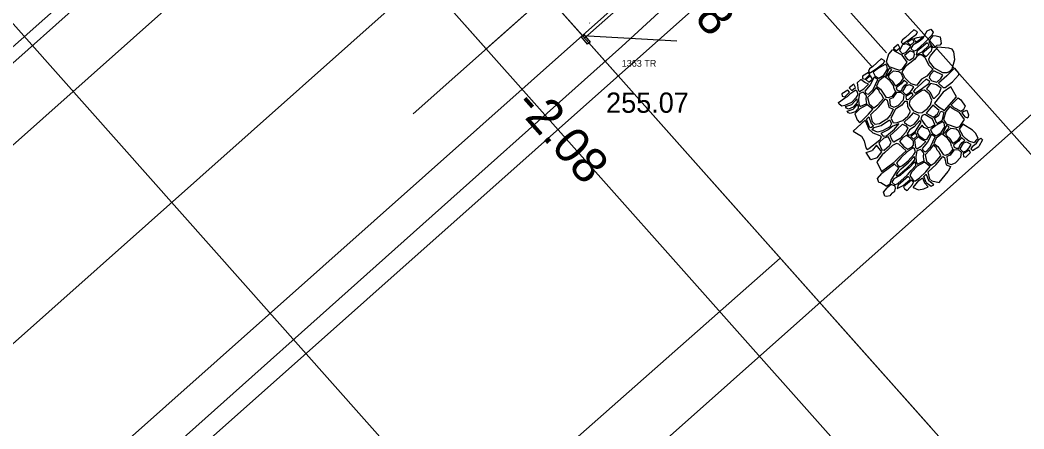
# Model space of a CAD drawing. Extents: x 49683 to 58852, y 49525 to 54803.
# Drawn here: x 53855 to 54003.9, y 51774.1 to 51834.7 of the extents above; entities that cross this region are included whole.
import ezdxf

# ---------------------------------------------------------------- set-up
doc = ezdxf.new("R2010")
doc.units = 0
for name, color, linetype in [('Level 11', 7, 'Continuous'), ('Level 13', 7, 'Continuous'), ('Level 15', 7, 'Continuous'), ('Level 16', 7, 'Continuous'), ('Level 19', 7, 'Continuous'), ('Level 20', 7, 'Continuous'), ('Level 27', 7, 'Continuous'), ('Level 29', 7, 'Continuous'), ('Level 3', 7, 'Continuous'), ('Level 32', 7, 'Continuous'), ('Level 33', 7, 'Continuous'), ('Level 5', 7, 'Continuous'), ('Level 50', 7, 'Continuous'), ('Level 53', 7, 'Continuous'), ('Level 61', 7, 'Continuous'), ('Level 63', 7, 'Continuous'), ('Level 8', 7, 'Continuous')]:
    doc.layers.add(name, color=color, linetype=linetype)

msp = doc.modelspace()

# ---------------------------------------------------------------- linework, layer by layer
at = {"layer": 'Level 11'}
for p, q in [((53944.24, 51830.77), (54450.3, 52297.6)), ((53245.86, 51207.55), (53944.24, 51830.77))]:
    msp.add_line(p, q, dxfattribs=at)
at = {"layer": 'Level 13'}
msp.add_line((53681.55, 51593.39), (53996.93, 51873.72), dxfattribs=at)
at = {"layer": 'Level 15'}
for p, q in [((53460.73, 51466.68), (53909.18, 51865.3)), ((53938.41, 51832.41), (53909.18, 51865.3)), ((53953.36, 51845.7), (53938.41, 51832.41)), ((53939.46, 51834.29), (53939.52, 51834.21)), ((53938.41, 51832.41), (53489.97, 51433.79)), ((53938.41, 51832.41), (53952.39, 51831.59))]:
    msp.add_line(p, q, dxfattribs=at)
at = {"layer": 'Level 16'}
for points in [[(53988.15, 51832.94), (53987.57, 51833.26), (53986.35, 51832.1), (53985.88, 51831.74), (53985.69, 51831.42), (53985.94, 51831.17), (53987.03, 51831.91), (53987.96, 51832.6)], [(53987.36, 51831.91), (53986.66, 51831.37), (53987.08, 51830.98), (53987.62, 51831.44)], [(53985.24, 51831.05), (53984.55, 51830.52), (53984.96, 51830.12), (53985.51, 51830.58)], [(53987.12, 51830.84), (53986.46, 51831.16), (53985.92, 51831.03), (53985.44, 51830.19), (53985.92, 51829.68), (53986.46, 51829.95), (53986.81, 51830.34)], [(53986.19, 51829.44), (53986.63, 51828.83), (53986.95, 51828.73), (53987.56, 51829.15), (53987.69, 51829.59), (53987.63, 51829.9), (53987.04, 51830.14)], [(53989.58, 51831.31), (53988.08, 51830.06), (53987.95, 51829.55), (53988.82, 51829.98), (53989.83, 51830.9), (53989.82, 51831.06)], [(53990.08, 51830.81), (53988.88, 51829.78), (53989, 51829.51), (53989.43, 51829.27), (53990.21, 51830.13), (53990.32, 51830.51)], [(53983.28, 51828.64), (53982.71, 51828.96), (53981.49, 51827.81), (53981.02, 51827.44), (53980.83, 51827.12), (53981.08, 51826.87), (53982.17, 51827.61), (53983.09, 51828.3)], [(53983.32, 51828.09), (53982.36, 51827.56), (53981.53, 51826.94), (53981.84, 51826.39), (53982.37, 51826.06), (53983.15, 51826.52), (53983.65, 51827.39), (53983.58, 51827.93)], [(53983.9, 51827.54), (53983.36, 51826.44), (53983.54, 51826.38), (53984.14, 51827.08), (53984.32, 51827.37)], [(53986.01, 51826.05), (53985.51, 51825.31), (53984.91, 51824.88), (53984.47, 51825.59), (53983.9, 51826.07), (53983.84, 51826.35), (53984.02, 51826.66), (53984.55, 51827.16), (53985.37, 51827.05), (53985.63, 51826.84)], [(53991.9, 51826.5), (53990.56, 51827.17), (53989.99, 51826.58), (53989.86, 51826.12), (53990.23, 51825.67), (53990.97, 51825.5), (53991.57, 51826.02)], [(53979.72, 51825.87), (53979.17, 51825.39), (53979.3, 51824.3), (53979.54, 51824.09), (53980.18, 51824.48), (53980.85, 51825.19), (53980.3, 51825.43)], [(53980.84, 51826.92), (53979.95, 51826.38), (53979.98, 51826.02), (53980.36, 51825.93), (53981.06, 51826.62)], [(53981.71, 51826.23), (53981.08, 51825.07), (53980.29, 51824.17), (53980.48, 51823.8), (53980.83, 51823.69), (53981.53, 51824.38), (53982.22, 51825.9)], [(53981.17, 51826.41), (53980.47, 51825.87), (53980.89, 51825.48), (53981.43, 51825.94)], [(53986.15, 51825.8), (53985.72, 51825.24), (53984.94, 51824.65), (53985.05, 51824.33), (53985.37, 51824.18), (53985.76, 51824.19), (53985.89, 51824.58), (53986.23, 51825.06), (53986.65, 51825.34)], [(53989.98, 51825.6), (53989.4, 51825.93), (53988.18, 51824.77), (53987.71, 51824.4), (53987.52, 51824.09), (53987.77, 51823.84), (53988.86, 51824.57), (53989.79, 51825.27)], [(53977.81, 51824.3), (53976.92, 51823.75), (53976.94, 51823.4), (53977.33, 51823.3), (53978.03, 51824)], [(53978.67, 51825.17), (53977.98, 51824.64), (53978.39, 51824.25), (53978.94, 51824.7)], [(53980.05, 51824.02), (53979.54, 51823.8), (53979.36, 51822.97), (53979.44, 51822.2), (53979.63, 51821.85), (53980.6, 51822.33), (53980.53, 51822.92), (53980.55, 51823.45)], [(53981.92, 51824.66), (53981.4, 51823.92), (53980.73, 51823.21), (53980.94, 51822.28), (53981.65, 51821.67), (53982.26, 51822.1), (53983.06, 51823.07), (53982.82, 51823.62), (53982.53, 51823.91), (53982.39, 51824.3)], [(53987.59, 51824.77), (53986.93, 51825.1), (53986.4, 51824.96), (53985.91, 51824.12), (53986.4, 51823.61), (53986.93, 51823.88), (53987.28, 51824.27)], [(53989.18, 51824.3), (53988.83, 51824.23), (53987.76, 51823.53), (53986.98, 51822.75), (53986.89, 51822.3), (53987.01, 51821.99), (53987.5, 51821.3), (53988.26, 51820.91), (53988.83, 51820.97), (53989.59, 51821.56), (53990.04, 51822.14), (53990.24, 51822.8), (53989.86, 51823.77)], [(53991.65, 51824.59), (53990.96, 51825.08), (53990.07, 51825.28), (53989.47, 51824.51), (53989.98, 51824.05), (53990.43, 51823.09), (53990.66, 51823.09), (53991.34, 51823.78)], [(53993.08, 51824.81), (53991.94, 51823.99), (53990.65, 51822.38), (53991.32, 51821.78), (53992.14, 51821.28), (53993.89, 51823.32)], [(53983.36, 51822.99), (53983.63, 51822.82), (53983.85, 51821.76), (53984.52, 51821.49), (53984.13, 51820.64), (53983.59, 51819.97), (53982.47, 51819.3), (53981.83, 51819.18), (53981.47, 51819.6), (53981.18, 51820.69), (53982.4, 51821.8)], [(53985.01, 51823.93), (53984.48, 51823.16), (53983.95, 51822.95), (53984.05, 51822), (53984.61, 51821.78), (53985.25, 51822.02), (53986.05, 51822.85), (53986.14, 51823.56), (53985.68, 51823.94)], [(53986.22, 51822.59), (53985.82, 51822.08), (53984.88, 51821.5), (53984.18, 51820.16), (53984.52, 51819.52), (53984.96, 51819.45), (53985.94, 51819.78), (53986.68, 51820.45), (53987.1, 51821.11), (53986.7, 51821.84), (53986.66, 51822.6)], [(53987.28, 51823.89), (53986.4, 51823.34), (53986.42, 51822.98), (53986.81, 51822.89), (53987.5, 51823.58)], [(53990.38, 51822.07), (53989.41, 51820.9), (53990.51, 51820.29), (53991.1, 51820.78), (53991.35, 51821.29)], [(53991.58, 51821.18), (53992.01, 51821.03), (53991.73, 51819.74), (53990.98, 51819.36), (53990.65, 51820.13), (53991.3, 51820.61)], [(53995.12, 51819.93), (53994.35, 51820.99), (53993.35, 51821.53), (53992.93, 51821.85), (53992.33, 51821.12), (53991.97, 51819.94), (53992.4, 51819.31), (53993.94, 51818.75), (53994.42, 51818.93)], [(53980.88, 51820.34), (53981.26, 51819.35), (53981.59, 51818.97), (53981.22, 51818.71), (53981.01, 51818.79), (53980.57, 51820.01)], [(53983.96, 51819.88), (53984.26, 51819.34), (53984.03, 51818.88), (53982.91, 51818.27), (53982.18, 51818.07), (53981.42, 51818.42), (53981.72, 51818.78), (53982.72, 51819.07)], [(53987.46, 51820.92), (53986.86, 51820.18), (53986.16, 51819.56), (53986.56, 51819.2), (53987.04, 51818.95), (53987.65, 51819.26), (53988.2, 51819.94), (53988.42, 51820.5)], [(53988.45, 51819.81), (53987.61, 51818.86), (53986.92, 51818.42), (53986.61, 51817.8), (53986.85, 51817.61), (53987.17, 51817.73), (53987.83, 51818.23), (53988.65, 51819.54)], [(53990.68, 51819.21), (53990.37, 51819.97), (53989.2, 51820.69), (53988.81, 51820.54), (53988.61, 51820.03), (53989.19, 51819.18), (53989.67, 51818.78), (53990.21, 51818.85)], [(53991.84, 51819.58), (53990.87, 51819.05), (53990.05, 51818.43), (53990.35, 51817.87), (53990.88, 51817.54), (53991.66, 51818.01), (53992.17, 51818.88), (53992.09, 51819.42)], [(53985.37, 51819.31), (53984.46, 51818.95), (53983.75, 51818.41), (53982.69, 51817.85), (53983.05, 51817.45), (53983.53, 51817.54), (53984.71, 51818.49)], [(53985.9, 51819.26), (53986.4, 51819), (53986.69, 51818.64), (53986.36, 51818.01), (53985.53, 51817.14), (53984.63, 51816.57), (53984.3, 51816.96), (53984.09, 51817.57), (53985.06, 51818.48)], [(53990.05, 51817.89), (53989.69, 51818.49), (53989.08, 51818.78), (53988.81, 51819.12), (53988.22, 51818.41), (53988.09, 51817.98), (53988.31, 51817.57), (53989.08, 51817.04), (53989.52, 51816.97)], [(53992.41, 51819.03), (53991.87, 51817.93), (53992.05, 51817.86), (53992.66, 51818.56), (53992.83, 51818.86)], [(53994.52, 51817.54), (53994.03, 51816.8), (53993.43, 51816.37), (53992.98, 51817.08), (53992.41, 51817.56), (53992.35, 51817.84), (53992.53, 51818.15), (53993.06, 51818.65), (53993.88, 51818.54), (53994.14, 51818.33)], [(53983.78, 51817.39), (53983.13, 51817.18), (53982.47, 51816.58), (53982.38, 51816.43), (53982.84, 51815.46), (53983.18, 51815.38), (53983.99, 51816.09), (53984.24, 51816.52)], [(53987.55, 51816.14), (53987.53, 51816.73), (53987.02, 51817.23), (53986.47, 51817.56), (53985.94, 51817.28), (53985.47, 51816.68), (53986.1, 51815.96), (53986.68, 51815.54), (53987.31, 51815.87)], [(53987.83, 51817.97), (53987.14, 51817.43), (53987.55, 51817.04), (53988.1, 51817.5)], [(53988.23, 51817.36), (53987.68, 51816.88), (53987.82, 51815.79), (53988.05, 51815.58), (53988.69, 51815.97), (53989.36, 51816.68), (53988.81, 51816.92)], [(53990.22, 51817.72), (53989.59, 51816.56), (53988.8, 51815.65), (53988.99, 51815.29), (53989.35, 51815.17), (53990.04, 51815.87), (53990.73, 51817.39)], [(53994.66, 51817.29), (53994.23, 51816.73), (53993.45, 51816.14), (53993.57, 51815.82), (53993.88, 51815.67), (53994.27, 51815.68), (53994.41, 51816.07), (53994.74, 51816.55), (53995.16, 51816.82)], [(53996.11, 51816.26), (53995.45, 51816.58), (53994.91, 51816.45), (53994.43, 51815.61), (53994.91, 51815.1), (53995.44, 51815.37), (53995.79, 51815.75)], [(53987.48, 51815.76), (53986.6, 51815.17), (53985.69, 51814.31), (53984.99, 51813.54), (53985.2, 51813.19), (53985.5, 51812.94), (53985.91, 51813.1), (53986.75, 51813.81), (53987.6, 51814.75), (53987.83, 51815.13), (53987.68, 51815.59)], [(53988.56, 51815.51), (53988.05, 51815.29), (53987.87, 51814.46), (53987.95, 51813.69), (53988.14, 51813.34), (53989.11, 51813.82), (53989.04, 51814.4), (53989.07, 51814.94)], [(53990.43, 51816.15), (53989.92, 51815.41), (53989.24, 51814.69), (53989.46, 51813.77), (53990.16, 51813.15), (53990.77, 51813.59), (53991.57, 51814.56), (53991.33, 51815.11), (53991.04, 51815.4), (53990.9, 51815.79)], [(53993.53, 51815.42), (53992.99, 51814.65), (53992.46, 51814.44), (53992.56, 51813.49), (53993.12, 51813.27), (53993.77, 51813.51), (53994.56, 51814.34), (53994.65, 51815.05), (53994.19, 51815.43)], [(53995.79, 51815.38), (53994.91, 51814.83), (53994.93, 51814.47), (53995.32, 51814.38), (53996.01, 51815.07)], [(53989.99, 51812.99), (53989.16, 51813.63), (53988.08, 51813.04), (53987.28, 51812.19), (53986.97, 51811.64), (53987.33, 51811.13), (53987.54, 51810.85), (53987.85, 51810.83), (53988.44, 51811.3), (53989.36, 51812.2)], [(53986.76, 51811.47), (53985.26, 51810.22), (53985.13, 51809.71), (53986, 51810.14), (53987.02, 51811.06), (53987, 51811.22)]]:
    msp.add_lwpolyline(points, close=True, dxfattribs=at)
for points in [[(53988.94, 51831.98), (53989.57, 51833.09), (53990.08, 51833.34), (53990.46, 51832.91), (53990.24, 51832.44), (53989.18, 51831.33)], [(53988.94, 51831.98), (53988.36, 51831.49), (53987.41, 51830.98), (53987.15, 51830.47), (53987.57, 51830.08), (53988.04, 51830.29), (53989.18, 51831.33)], [(53987.74, 51831.72), (53987.69, 51831.82), (53987.63, 51831.94), (53988.06, 51832.09), (53988.96, 51832.23)], [(53987.74, 51831.69), (53987.8, 51831.56), (53987.85, 51831.44), (53988.25, 51831.65), (53988.96, 51832.23)], [(53988.92, 51832.2), (53988.86, 51832.14)], [(53990.43, 51832.38), (53990.09, 51832.03), (53989.79, 51831.48), (53990.15, 51830.97), (53990.36, 51830.69), (53990.67, 51830.67), (53991.01, 51830.94)], [(53990.43, 51832.38), (53990.91, 51832.36), (53991.51, 51832.18), (53991.61, 51831.56), (53991.65, 51831.21), (53991.44, 51830.98), (53991.01, 51830.94)], [(53984.35, 51830.28), (53983.82, 51829.64), (53983.46, 51828.45), (53983.89, 51827.82), (53985.43, 51827.26), (53985.91, 51827.44), (53986.61, 51828.44), (53985.84, 51829.5), (53984.83, 51830.04), (53984.46, 51830.32)], [(53992.67, 51826.96), (53992.49, 51826.88), (53991.9, 51826.87), (53990.64, 51827.57), (53989.93, 51828.49), (53989.81, 51828.94), (53990.05, 51829.38), (53990.75, 51830.22)], [(53990.76, 51830.23), (53991.12, 51830.68)], [(53992.67, 51826.96), (53992.87, 51827.04), (53993.28, 51827.46), (53993.67, 51828.84), (53993.51, 51829.99), (53993.27, 51830.39), (53992.8, 51830.54), (53991.12, 51830.68)], [(53989.26, 51829.11), (53988.72, 51829.52), (53988.36, 51829.51), (53988.01, 51829.3), (53987.66, 51828.86), (53986.31, 51827.75), (53985.8, 51827.02), (53986.27, 51826.12)], [(53989.28, 51829.08), (53989.77, 51828.06), (53990.42, 51827.39), (53989.52, 51826.36), (53988.73, 51825.91), (53988, 51824.99), (53987.21, 51825.24), (53986.72, 51825.62), (53986.3, 51826.09)], [(53992.47, 51826.42), (53993.63, 51827.55), (53994.22, 51826.81), (53994.2, 51826.52), (53993.3, 51825.51)], [(53984.66, 51824.5), (53984.56, 51824.99), (53984.06, 51825.69), (53983.25, 51826.33), (53982.38, 51825.68), (53982.02, 51824.9), (53982.65, 51824.45), (53983.41, 51823.26)], [(53992.47, 51826.42), (53991.24, 51825.35), (53991.93, 51824.7), (53992.22, 51824.7), (53993.3, 51825.51)], [(53978.35, 51822.45), (53979.09, 51823.26), (53979.31, 51823.64), (53979.17, 51824.1), (53978.97, 51824.28), (53978.09, 51823.68), (53977.72, 51823.34)], [(53984.67, 51824.47), (53984.84, 51824.06), (53984.3, 51823.34), (53983.76, 51823.14), (53983.44, 51823.23)], [(53978.35, 51822.45), (53977.34, 51822.02), (53976.91, 51821.94), (53976.52, 51822.23), (53976.42, 51822.48), (53977.28, 51823.11), (53977.72, 51823.34)], [(53978.37, 51822.19), (53979.11, 51822.99), (53979.15, 51822.47), (53978.6, 51821.75)], [(53993.12, 51822.12), (53994.17, 51823.18), (53994.55, 51822.88), (53995.2, 51821.92), (53994.96, 51821.45)], [(53978.6, 51821.75), (53977.88, 51821.48), (53977.61, 51821.63), (53977.43, 51821.86), (53978.37, 51822.19)], [(53978.86, 51821.08), (53978.15, 51820.81), (53977.88, 51820.95), (53977.7, 51821.19), (53978.58, 51821.5)], [(53978.86, 51821.08), (53979.38, 51821.63), (53979.35, 51821.93), (53979.2, 51822.19), (53978.58, 51821.5)], [(53979.52, 51819.48), (53979.92, 51819.81), (53980.85, 51820.71), (53981.48, 51821.5), (53980.65, 51822.14), (53979.57, 51821.55), (53978.82, 51820.76)], [(53993.12, 51822.12), (53993.52, 51821.73), (53994.55, 51821.19), (53994.98, 51821.47)], [(53995.03, 51821.2), (53994.7, 51820.93), (53995.14, 51820.32), (53995.59, 51820.18)], [(53995.03, 51821.2), (53995.43, 51821.33), (53995.71, 51820.63), (53995.59, 51820.18)], [(53980.35, 51819.84), (53978.58, 51818.22), (53979.8, 51817.49), (53980.22, 51816.8), (53980.46, 51815.74), (53980.64, 51815.5), (53980.91, 51815.57)], [(53978.82, 51820.76), (53979.16, 51819.88), (53979.52, 51819.48)], [(53980.35, 51819.84), (53980.9, 51818.51), (53981.52, 51817.99), (53982.53, 51817.59), (53982.74, 51817.38), (53982.52, 51816.86), (53980.91, 51815.57)], [(53994.84, 51819.27), (53994.31, 51818.5), (53994.79, 51817.61)], [(53996.8, 51816.84), (53997.11, 51817.17), (53996.73, 51817.92), (53996.29, 51818.34), (53994.84, 51819.27)], [(53993.17, 51815.99), (53993.07, 51816.48), (53992.57, 51817.18), (53991.76, 51817.82), (53990.89, 51817.16), (53990.53, 51816.39), (53991.16, 51815.94), (53991.92, 51814.75)], [(53996.8, 51816.84), (53996.52, 51816.48), (53995.72, 51816.73), (53995.24, 51817.11), (53994.81, 51817.58)], [(53996.81, 51816.35), (53997.22, 51816.97), (53997.52, 51817.18), (53997.79, 51816.95), (53997.23, 51815.96)], [(53982.16, 51814.28), (53981.19, 51813.95), (53980.5, 51815.03), (53981.38, 51815.36)], [(53982.16, 51814.28), (53982.83, 51815.14), (53982.03, 51816.15), (53981.38, 51815.36)], [(53984.69, 51813.65), (53985.38, 51814.29), (53986.42, 51815.31), (53985.35, 51816.29), (53985.03, 51816.38), (53984.43, 51816.09), (53983.29, 51815.05)], [(53993.18, 51815.96), (53993.35, 51815.55), (53992.81, 51814.83), (53992.27, 51814.62), (53991.95, 51814.72)], [(53996.81, 51816.35), (53996.22, 51815.89), (53996.03, 51815.58), (53996.28, 51815.33), (53997.23, 51815.96)], [(53983.28, 51815.03), (53982.9, 51814.71), (53982.07, 51813.68), (53982.78, 51812.21), (53984.67, 51813.63)], [(53985.72, 51812.64), (53986.75, 51813.54), (53987.62, 51814.48), (53987.66, 51813.96), (53987.15, 51813.3), (53986.63, 51812.81), (53986.04, 51812.3)], [(53986.63, 51811.73), (53987.17, 51812.36), (53987.89, 51813.12), (53987.86, 51813.42), (53987.71, 51813.68), (53986.9, 51812.77), (53986.17, 51812.18)], [(53990.07, 51810.99), (53989.98, 51811.09), (53989.7, 51812.18), (53990.91, 51813.28), (53991.87, 51814.48), (53992.14, 51814.31), (53992.36, 51813.24), (53993.03, 51812.98), (53992.69, 51812.25)], [(53983.49, 51810.04), (53984.06, 51810.41), (53984.2, 51810.94), (53984.95, 51812.15), (53985.38, 51812.75), (53984.72, 51813.34), (53982.82, 51811.93)], [(53986.15, 51812.16), (53985.55, 51811.65), (53984.59, 51811.13), (53984.33, 51810.63), (53984.75, 51810.24), (53985.23, 51810.45), (53986.6, 51811.7)], [(53985.69, 51812.61), (53985.18, 51812.02), (53984.98, 51811.72), (53985.03, 51811.6), (53985.44, 51811.81), (53986.02, 51812.28)], [(53990.13, 51810.93), (53990.24, 51810.84), (53991.34, 51810.61), (53992.69, 51812.25)], [(53983.49, 51810.04), (53982.7, 51810.53), (53982.39, 51810.6), (53982.17, 51811.2), (53982.82, 51811.93)], [(53986.61, 51809.43), (53987.39, 51810.29), (53987.51, 51810.67), (53987.26, 51810.97), (53986.06, 51809.94), (53986.18, 51809.67), (53986.61, 51809.43)], [(53987.95, 51810.39), (53988.34, 51810.88), (53988.87, 51811.31), (53989.17, 51810.57)], [(53988.29, 51809.49), (53989.09, 51809.68), (53989.72, 51809.98), (53989.17, 51810.57)], [(53989.4, 51810.62), (53989.08, 51811.5), (53989.39, 51811.83), (53989.75, 51810.88)], [(53989.4, 51810.62), (53990.15, 51810.05), (53990.55, 51810.25), (53989.75, 51810.88)], [(53984.33, 51809.03), (53984.03, 51808.62), (53983.59, 51808.51), (53983.28, 51808.59), (53983.06, 51809.18), (53983.6, 51809.79)], [(53984.33, 51809.03), (53984.75, 51809.31), (53984.87, 51809.75), (53984.81, 51810.06), (53984.22, 51810.3), (53983.6, 51809.79)], [(53987.48, 51809.84), (53987.93, 51810.38)], [(53987.48, 51809.84), (53988.29, 51809.49)]]:
    msp.add_lwpolyline(points, dxfattribs=at)
at = {"layer": 'Level 19'}
msp.add_line((52714.15, 50773.62), (54181.77, 52078.16), dxfattribs=at)
at = {"layer": 'Level 20'}
msp.add_line((53913.31, 51820.8), (54191.07, 52067.7), dxfattribs=at)
at = {"layer": 'Level 27'}
for p, q in [((53961.77, 51853.17), (53938.41, 51832.41)), ((53962.1, 51852.8), (53938.74, 51832.04))]:
    msp.add_line(p, q, dxfattribs=at)
msp.add_lwpolyline([(53939.57, 51831.42), (53939.18, 51831.1), (53938.22, 51832.25), (53938.6, 51832.57)], close=True, dxfattribs=at)
at = {"layer": 'Level 29'}
msp.add_line((52714.15, 50773.62), (54181.77, 52078.16), dxfattribs=at)
at = {"layer": 'Level 3'}
msp.add_line((53449.72, 51471.81), (53898.74, 51870.57), dxfattribs=at)
at = {"layer": 'Level 33'}
msp.add_line((53711.35, 51559.67), (54231.6, 52022.1), dxfattribs=at)
at = {"layer": 'Level 5'}
msp.add_line((53900.07, 51869.4), (53451.19, 51470.16), dxfattribs=at)
at = {"layer": 'Level 50'}
for p, q in [((53872.47, 51963.79), (54031.92, 51784.41)), ((53824.14, 51960.97), (54023.45, 51736.74)), ((53835.1, 51930.57), (53994.55, 51751.19)), ((53797.73, 51897.35), (53957.18, 51717.97))]:
    msp.add_line(p, q, dxfattribs=at)
at = {"layer": 'Level 53'}
msp.add_line((53857.36, 51923.59), (53990.23, 51774.11), dxfattribs=at)
at = {"layer": 'Level 61'}
msp.add_line((53517.82, 51402.46), (53967.76, 51799.4), dxfattribs=at)
at = {"layer": 'Level 63'}
for p, q in [((53924.13, 51830.42), (53948.05, 51851.68)), ((53914.83, 51840.88), (53924.13, 51830.42))]:
    msp.add_line(p, q, dxfattribs=at)
at = {"layer": 'Level 8'}
for p, q in [((53962.33, 51853.67), (53983.51, 51829.84)), ((53960.09, 51851.68), (53981.28, 51827.84))]:
    msp.add_line(p, q, dxfattribs=at)

# ---------------------------------------------------------------- texts
at = {"layer": 'Level 32'}
msp.add_text('255.07', height=3, dxfattribs=at).set_placement((53941.92, 51820.94))
at = {"layer": 'Level 61'}
msp.add_text('1363 TR', height=1, dxfattribs=at).set_placement((53944.24, 51827.77))
at = {"layer": 'Level 63'}
for p in [(53946.86, 51843.9), (53928.15, 51821.97)]:
    msp.add_text('-2.08', height=5.25, rotation=311.6334, dxfattribs=at).set_placement(p)

doc.saveas('drawing.dxf')
